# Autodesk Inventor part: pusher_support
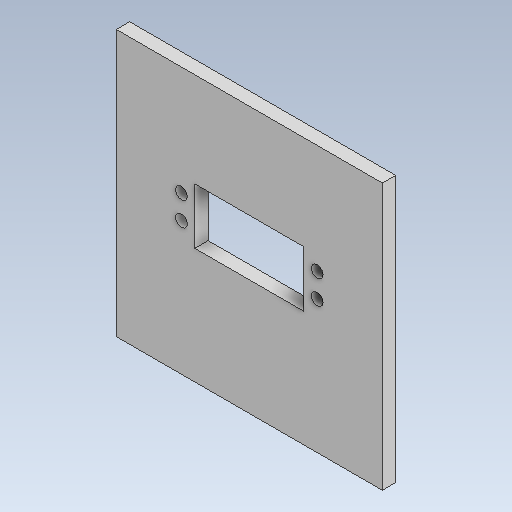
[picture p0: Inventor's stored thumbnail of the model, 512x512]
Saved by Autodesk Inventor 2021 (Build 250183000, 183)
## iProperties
Created: 2026-10
Part Number: pusher_support
Material: Generic
Document SubType Name: Modeling
Designer: alolo
Density: 1 g/cm^3
Appearance: Default
Author: alolo
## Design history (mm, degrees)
sketch "Sketch1"
  geometry: L1 (0, 0)-(41, 0); L2 (41, 0)-(41, 21); L3 (41, 21)-(0, 21); L4 (0, 21)-(0, 0); L5 (20.5, 0)-(20.5, 21); L6 (-29.5, 56.5)-(70.5, 56.5); L7 (70.5, 56.5)-(70.5, -43.5); L8 (70.5, -43.5)-(-29.5, -43.5); L9 (-29.5, -43.5)-(-29.5, 56.5); C1 r 2.2 at (-5, 6.5); C2 r 2.2 at (-5, 15.5); C3 r 2.2 at (46, 6.5); C4 r 2.2 at (46, 15.5); 1 further point
  constraints: 18 end point, 4 centre point, 4 parallel, 3 midpoint, 2 horizontal, 2 perpendicular, 2 symmetric about line, 2 vertical alignment, 2 other
  dimensions: "d0" = 41 distance of L3.end L2.end; "d1" = 4.4 diameter of C1; "d2" = 21 distance of L1.end L2.end; "d3" = 5 distance from line of L4 C1.centre; "d4" = 14.5 distance from line of L3 C1.centre; "d5" = 4.4 diameter of C2; "d6" = 5.5 distance from line of L3 C2.centre; "d7" = 100 distance of L6.end L7.end; "d8" = 43.5 distance between parallel lines of L1 L8; "d9" = 100 distance of L6.start L6.end
extrude "Extrusion1" new body sketch "Sketch1" distance "d10" = 5 (= wood_thickness); taper "d11" = 0 deg
body "Solid1"
other parameters: "slide_length" = 195 [user parameter], "slide_angle" = 7 deg [user parameter], "slide_width" = 65 [user parameter], "wood_thickness" = 5 [user parameter; used in 1 equation term], "aclyric_thickness" = 6 [user parameter]
